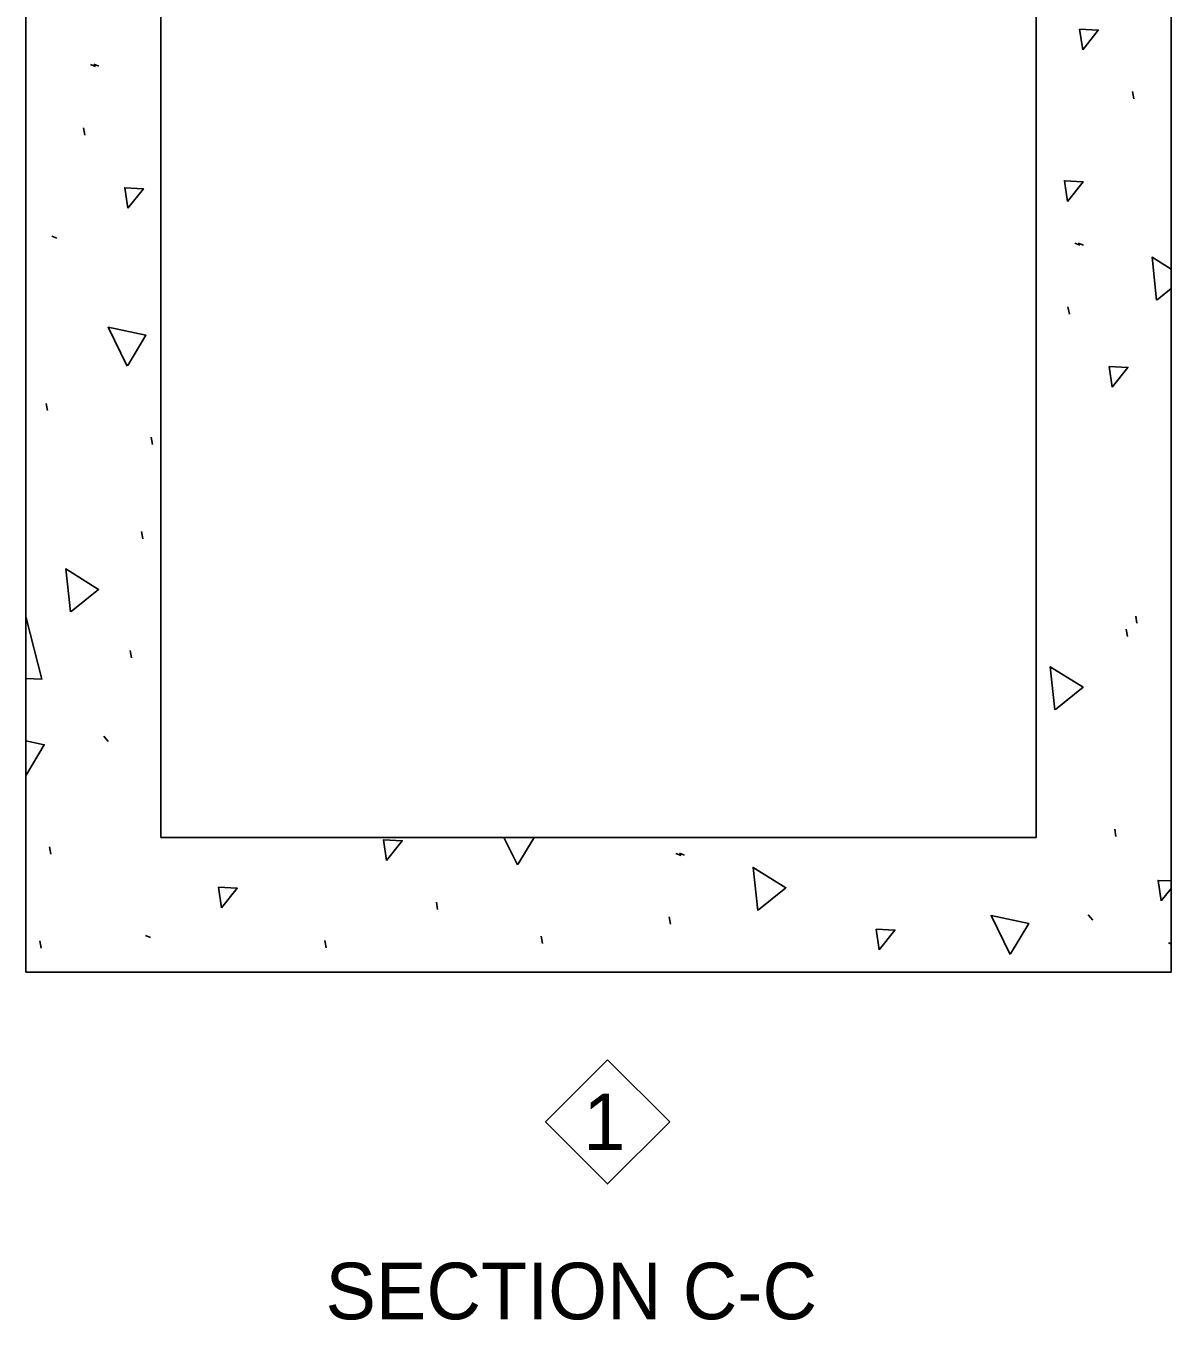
# Model space of a CAD drawing. Extents: x 49991.4 to 50029.7, y 49987.6 to 50011.4.
# Drawn here: x 50026.442 to 50028.062, y 49990.52 to 49992.349 of the extents above; entities that cross this region are included whole.
import ezdxf

# ---------------------------------------------------------------- set-up
doc = ezdxf.new("R2010")
doc.units = 0
for name, color, linetype in [('Level 1', 7, 'Continuous'), ('Level 2', 7, 'Continuous'), ('Level 20', 7, 'Continuous'), ('Level 9', 7, 'Continuous')]:
    doc.layers.add(name, color=color, linetype=linetype)

msp = doc.modelspace()

# ---------------------------------------------------------------- linework, layer by layer
at = {"layer": 'Level 1'}
for p, q in [((50026.4424, 49991.0114), (50026.4424, 49993.1685)), ((50028.0624, 49993.1696), (50028.0624, 49991.0114)), ((50026.6331, 49991.2021), (50026.6331, 49992.9949)), ((50027.8717, 49992.9949), (50027.8717, 49991.2021)), ((50026.6331, 49991.2021), (50027.8717, 49991.2021)), ((50026.4424, 49991.0114), (50028.0624, 49991.0114))]:
    msp.add_line(p, q, dxfattribs=at)
at = {"layer": 'Level 20'}
msp.add_lwpolyline([(50027.2653, 49990.8876), (50027.3531, 49990.7999), (50027.2653, 49990.7121), (50027.1775, 49990.7999)], close=True, dxfattribs=at)
at = {"layer": 'Level 9'}
for p, q in [((50026.5337, 49992.2947), (50026.5407, 49992.2918)), ((50026.5385, 49992.2951), (50026.5456, 49992.2922)), ((50028.0094, 49992.2462), (50028.0076, 49992.2564)), ((50026.5258, 49992.1948), (50026.5239, 49992.205)), ((50026.479, 49992.0521), (50026.486, 49992.0492)), ((50027.9263, 49992.042), (50027.9333, 49992.0391)), ((50027.9311, 49992.0423), (50027.9382, 49992.0394)), ((50027.9184, 49991.942), (50027.9165, 49991.9522)), ((50026.473, 49991.8055), (50026.4711, 49991.8157)), ((50026.6215, 49991.7575), (50026.6197, 49991.7678)), ((50026.6079, 49991.6243), (50026.6061, 49991.6346)), ((50028.0141, 49991.5047), (50028.0123, 49991.515)), ((50028.0005, 49991.4861), (50027.9987, 49991.4963)), ((50026.5918, 49991.456), (50026.59, 49991.4663)), ((50026.5526, 49991.3452), (50026.5588, 49991.3378)), ((50027.9844, 49991.2032), (50027.9826, 49991.2135)), ((50026.4776, 49991.1785), (50026.4758, 49991.1888)), ((50027.362, 49991.1794), (50027.3691, 49991.1765)), ((50027.3669, 49991.1798), (50027.3739, 49991.1769)), ((50027.0248, 49991.1001), (50027.023, 49991.1103)), ((50027.3541, 49991.0794), (50027.3523, 49991.0897)), ((50027.9452, 49991.0924), (50027.9514, 49991.0851)), ((50026.464, 49991.0453), (50026.4622, 49991.0556)), ((50026.6116, 49991.0632), (50026.6187, 49991.0603)), ((50026.8671, 49991.0461), (50026.8653, 49991.0563)), ((50027.1733, 49991.0521), (50027.1715, 49991.0624)), ((50028.0589, 49991.053), (50028.0624, 49991.0516))]:
    msp.add_line(p, q, dxfattribs=at)
for points in [[(50027.9373, 49992.3156), (50027.933, 49992.3447), (50027.9594, 49992.3434), (50027.9373, 49992.3156)], [(50027.9157, 49992.1012), (50027.9114, 49992.1303), (50027.9378, 49992.1289), (50027.9157, 49992.1012)], [(50026.5865, 49992.0915), (50026.5822, 49992.1205), (50026.6087, 49992.1192), (50026.5865, 49992.0915)], [(50028.0419, 49991.9614), (50028.0354, 49992.0222), (50028.0624, 49992.0054)], [(50028.0624, 49991.9779), (50028.0427, 49991.962)], [(50026.5858, 49991.8684), (50026.559, 49991.9232), (50026.6123, 49991.912), (50026.5865, 49991.8692)], [(50027.9791, 49991.8387), (50027.9748, 49991.8677), (50028.0013, 49991.8664), (50027.9791, 49991.8387)], [(50026.5054, 49991.5207), (50026.4989, 49991.5815), (50026.5452, 49991.5527), (50026.5063, 49991.5213)], [(50026.4426, 49991.5125), (50026.4424, 49991.5142)], [(50026.4424, 49991.4268), (50026.4648, 49991.4257), (50026.4426, 49991.5125)], [(50027.898, 49991.3824), (50027.8915, 49991.4432), (50027.9378, 49991.4144), (50027.8989, 49991.383)], [(50026.4424, 49991.3385), (50026.4684, 49991.333), (50026.4426, 49991.2902)], [(50026.9526, 49991.1695), (50026.9484, 49991.1986), (50026.9748, 49991.1973), (50026.9526, 49991.1695)], [(50027.1377, 49991.163), (50027.1185, 49991.2021)], [(50027.1614, 49991.2021), (50027.1383, 49991.1639)], [(50027.4776, 49991.0989), (50027.4711, 49991.1596), (50027.5174, 49991.1308), (50027.4785, 49991.0995)], [(50028.0483, 49991.1123), (50028.044, 49991.1413), (50028.0624, 49991.1404)], [(50026.7191, 49991.1025), (50026.7149, 49991.1315), (50026.7413, 49991.1302), (50026.7191, 49991.1025)], [(50028.0624, 49991.1299), (50028.0483, 49991.1123)], [(50027.8346, 49991.0366), (50027.8077, 49991.0915), (50027.861, 49991.0802), (50027.8352, 49991.0375)], [(50027.6495, 49991.0431), (50027.6453, 49991.0722), (50027.6717, 49991.0709), (50027.6495, 49991.0431)]]:
    msp.add_lwpolyline(points, dxfattribs=at)

# ---------------------------------------------------------------- texts
at = {"layer": 'Level 2'}
msp.add_text('SECTION C-C', height=0.08, dxfattribs=at).set_placement((50026.8662, 49990.5207))
at = {"layer": 'Level 20'}
msp.add_text('1', height=0.08, dxfattribs=at).set_placement((50027.231, 49990.7599))

doc.saveas('drawing.dxf')
